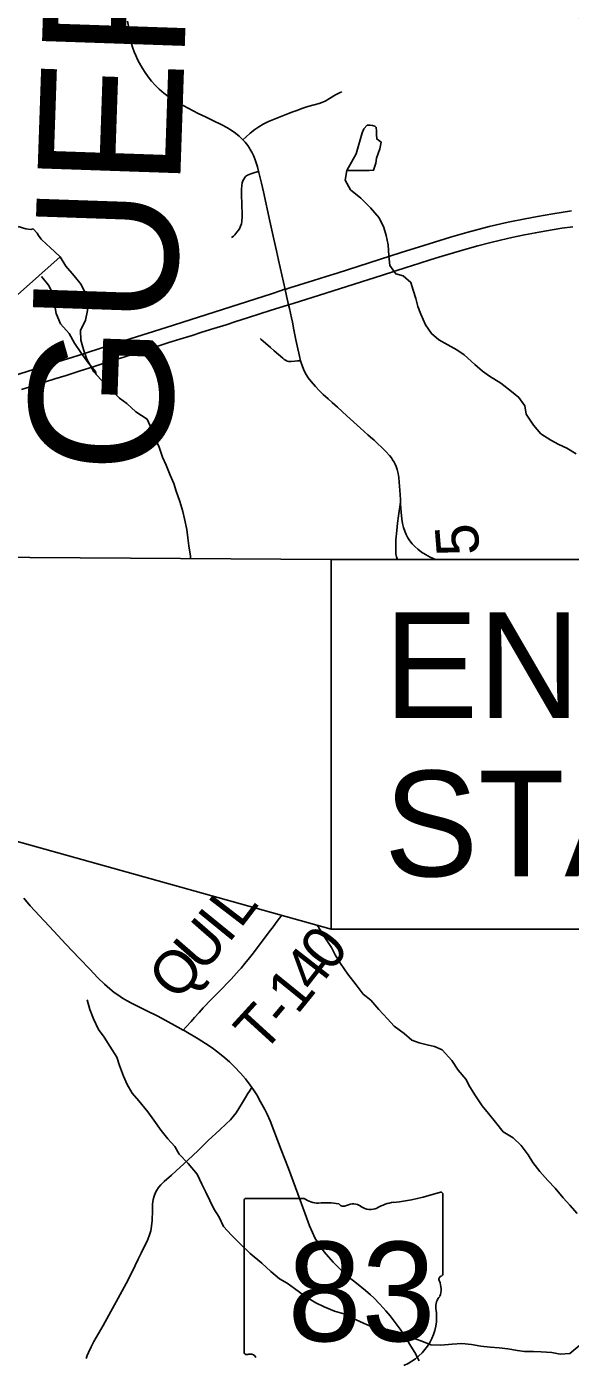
# Model space of a CAD drawing. Extents: x 0 to 34, y 0 to 22.
# Drawn here: x 28.753 to 29.474, y 15.353 to 17.117 of the extents above; entities that cross this region are included whole.
import ezdxf

# ---------------------------------------------------------------- set-up
doc = ezdxf.new("R2010")
doc.units = 0
for name, color, linetype in [('GM_X_Adjacent_County_Text', 7, 'Continuous'), ('GM_X_County_Road', 7, 'Continuous'), ('GM_X_Interstate_Route', 7, 'Continuous'), ('GM_X_Minor_Lake', 7, 'Continuous'), ('GM_X_Minor_River', 7, 'Continuous'), ('GM_X_Minor_River_Text', 7, 'Continuous'), ('GM_X_State_Location', 7, 'Continuous'), ('GM_X_State_Route', 7, 'Continuous'), ('GM_X_State_Shield', 7, 'Continuous'), ('GM_X_Township_Road', 7, 'Continuous'), ('GM_X_Township_Road_Text', 7, 'Continuous'), ('SH_Text', 7, 'Continuous')]:
    doc.layers.add(name, color=color, linetype=linetype)

msp = doc.modelspace()

# ---------------------------------------------------------------- linework, layer by layer
at = {"layer": 'GM_X_County_Road'}
for points in [[(28.9994, 16.9926), (28.9953, 16.9946), (28.9897, 16.9973), (28.9803, 17.002), (28.967, 17.0088), (28.9535, 17.0161), (28.9456, 17.021), (28.94, 17.0249), (28.9346, 17.029), (28.9286, 17.0342), (28.9233, 17.0394), (28.9184, 17.0449), (28.9138, 17.0507), (28.9099, 17.0563), (28.9059, 17.0625), (28.9022, 17.0688), (28.8998, 17.0735), (28.8973, 17.0788), (28.8952, 17.0838), (28.8933, 17.0896), (28.8918, 17.0946), (28.8905, 17.1014), (28.8882, 17.1154), (28.8866, 17.1241)], [(29.0394, 16.967), (29.0387, 16.9679), (29.0347, 16.9718), (29.0298, 16.9758), (29.0241, 16.9798), (29.0182, 16.9833), (29.0116, 16.9868), (28.9994, 16.9926)], [(29.0602, 16.925), (29.0587, 16.9311), (29.0563, 16.9389), (29.0538, 16.9453), (29.0514, 16.9504), (29.0492, 16.9542), (29.0482, 16.9557), (29.0458, 16.9593), (29.0424, 16.9637), (29.0394, 16.967)], [(29.116, 16.6737), (29.1144, 16.68), (29.1114, 16.6939), (29.1098, 16.7018), (29.1071, 16.7151), (29.1051, 16.725), (29.1039, 16.731), (29.1012, 16.7432), (29.1, 16.7482), (29.0973, 16.7602), (29.0954, 16.7686), (29.0867, 16.8074), (29.084, 16.8196), (29.0804, 16.8353), (29.0753, 16.859), (29.0666, 16.8978), (29.0639, 16.9093), (29.0605, 16.9238), (29.0602, 16.925)], [(29.1428, 16.6324), (29.1402, 16.6349), (29.1357, 16.6398), (29.13, 16.6464), (29.1262, 16.6512), (29.1232, 16.6558), (29.1207, 16.6607), (29.1184, 16.6664), (29.1162, 16.6728), (29.116, 16.6737)], [(29.2485, 16.4865), (29.2483, 16.49), (29.2476, 16.5024), (29.2468, 16.5129), (29.2462, 16.5191), (29.2453, 16.5247), (29.2442, 16.5296), (29.2427, 16.5338), (29.2414, 16.5367), (29.24, 16.5395), (29.238, 16.5425), (29.2365, 16.5451), (29.2338, 16.5485), (29.2291, 16.5536), (29.2247, 16.558), (29.2169, 16.5652), (29.2133, 16.5686), (29.2086, 16.5727), (29.2053, 16.5756), (29.1952, 16.5847), (29.1773, 16.6011), (29.1648, 16.6123), (29.158, 16.6185), (29.1524, 16.6235), (29.146, 16.6293), (29.1428, 16.6324)], [(29.2949, 16.4104), (29.2879, 16.4136), (29.2814, 16.417), (29.2762, 16.4203), (29.2713, 16.4241), (29.2672, 16.4277), (29.2639, 16.4313), (29.2608, 16.4351), (29.2582, 16.4392), (29.2559, 16.4435), (29.254, 16.448), (29.2524, 16.4529), (29.2511, 16.458), (29.2502, 16.4641), (29.2493, 16.4733), (29.2486, 16.4832), (29.2485, 16.4865)], [(28.8316, 15.3512), (28.833, 15.3552), (28.8346, 15.3592), (28.8382, 15.3664), (28.842, 15.3734), (28.8543, 15.395), (28.8618, 15.4086), (28.874, 15.431), (28.8847, 15.4506), (28.8921, 15.4649), (28.8966, 15.4745), (28.9006, 15.4829), (28.9022, 15.4862), (28.9044, 15.4907), (28.9077, 15.4973), (28.9124, 15.5068), (28.9153, 15.5138), (28.9172, 15.5204), (28.9183, 15.5266), (28.919, 15.5341), (28.9194, 15.5472), (28.9198, 15.5558), (28.9205, 15.5618), (28.9217, 15.5665), (28.9234, 15.571), (28.9252, 15.5744), (28.9276, 15.5776), (28.9307, 15.5813), (28.9349, 15.5857), (28.9446, 15.5943), (28.9511, 15.6), (28.9562, 15.6046), (28.9608, 15.6088), (28.9663, 15.6139), (28.9735, 15.6207), (28.9798, 15.6266), (28.9936, 15.6399), (29.0089, 15.6542), (29.0174, 15.6623), (29.0228, 15.6676), (29.0266, 15.6718), (29.0304, 15.6768), (29.0342, 15.6825), (29.039, 15.6905), (29.0428, 15.697), (29.046, 15.7022), (29.0483, 15.7055), (29.0515, 15.7102)]]:
    msp.add_lwpolyline(points, dxfattribs=at)
at = {"layer": 'GM_X_Interstate_Route'}
for points in [[(28.6908, 16.6398), (28.7743, 16.6663), (28.8211, 16.6811), (28.8744, 16.6981), (28.9377, 16.7182), (29.0774, 16.7628), (29.0904, 16.767), (29.0939, 16.7683), (29.0954, 16.7686), (29.0957, 16.7687), (29.1017, 16.7705), (29.1331, 16.7805), (29.1497, 16.7857), (29.1646, 16.7901), (29.2491, 16.8174), (29.2793, 16.827), (29.3149, 16.8379), (29.3364, 16.8441), (29.3658, 16.8519), (29.3912, 16.8578), (29.4137, 16.8624), (29.4302, 16.8655), (29.4504, 16.869), (29.475, 16.8727)], [(28.7459, 16.6357), (28.7631, 16.6412), (28.7779, 16.6459), (28.7903, 16.6499), (28.8051, 16.6545), (28.8223, 16.66), (28.8424, 16.6664), (28.8666, 16.6742), (28.8814, 16.6789), (28.9027, 16.6858), (28.9205, 16.6915), (28.9252, 16.693), (28.9412, 16.698), (28.956, 16.7027), (28.9721, 16.7077), (28.9851, 16.7118), (29.0011, 16.7168), (29.0171, 16.7218), (29.0301, 16.726), (29.0455, 16.7309), (29.0621, 16.7361), (29.0757, 16.7405), (29.1, 16.7482), (29.1059, 16.75), (29.1492, 16.7637), (29.2244, 16.7875), (29.2558, 16.7975), (29.2729, 16.803), (29.2889, 16.8081), (29.3038, 16.8126), (29.3186, 16.8171), (29.3336, 16.8214), (29.3509, 16.8262), (29.3666, 16.8304), (29.3811, 16.834), (29.3962, 16.8374), (29.4126, 16.8409), (29.4273, 16.8438), (29.4395, 16.846), (29.4623, 16.8496), (29.477, 16.8517)]]:
    msp.add_lwpolyline(points, dxfattribs=at)
at = {"layer": 'GM_X_Minor_Lake'}
for points in [[(29.1771, 16.9265), (29.2067, 16.9263), (29.2128, 16.9267), (29.2157, 16.9359), (29.2168, 16.9427), (29.2187, 16.9488), (29.2209, 16.9549), (29.2227, 16.964), (29.2193, 16.9663), (29.217, 16.9681), (29.2166, 16.9738), (29.2166, 16.9788), (29.2162, 16.9833), (29.2143, 16.9852), (29.2112, 16.9859), (29.2082, 16.9863), (29.2044, 16.9863)], [(29.2044, 16.9863), (29.1999, 16.9817), (29.1976, 16.9764), (29.1895, 16.9482), (29.1771, 16.9265)], [(29.1771, 16.9265), (29.2067, 16.9263), (29.2128, 16.9267), (29.2157, 16.9359), (29.2168, 16.9427), (29.2187, 16.9488), (29.2209, 16.9549), (29.2227, 16.964), (29.2193, 16.9663), (29.217, 16.9681), (29.2166, 16.9738), (29.2166, 16.9788), (29.2162, 16.9833), (29.2143, 16.9852), (29.2112, 16.9859), (29.2082, 16.9863), (29.204, 16.9863)], [(28.7416, 16.8522), (28.7394, 16.8495), (28.736, 16.8461), (28.7337, 16.8423), (28.7311, 16.8377), (28.7274, 16.8324), (28.7263, 16.8263), (28.7256, 16.8168), (28.726, 16.8096), (28.7264, 16.8047), (28.7235, 16.7948), (28.7269, 16.7853), (28.7338, 16.7732), (28.7404, 16.7615), (28.7973, 16.8116)], [(28.7973, 16.8116), (28.7835, 16.8248), (28.7797, 16.8282), (28.7721, 16.8353), (28.7683, 16.8399), (28.7667, 16.8433), (28.7614, 16.8489), (28.7583, 16.8481), (28.7515, 16.8489), (28.7416, 16.8522)]]:
    msp.add_lwpolyline(points, dxfattribs=at)
at = {"layer": 'GM_X_Minor_River'}
for points in [[(29.2654, 16.7677), (29.2623, 16.7779), (29.252, 16.7866), (29.2421, 16.7892), (29.2341, 16.8001), (29.2329, 16.813), (29.232, 16.8278), (29.2293, 16.8403), (29.2262, 16.8505), (29.22, 16.8634), (29.2086, 16.8766), (29.1956, 16.8894), (29.1822, 16.9007), (29.1749, 16.9136), (29.1771, 16.9265)], [(28.9701, 16.4116), (28.9698, 16.415), (28.9678, 16.4286), (28.9666, 16.4392), (28.965, 16.4502), (28.9619, 16.4642), (28.9599, 16.4741), (28.956, 16.4874), (28.951, 16.501), (28.9479, 16.5112), (28.9429, 16.5222), (28.9379, 16.5354), (28.9329, 16.546), (28.9283, 16.5593), (28.9225, 16.5718), (28.9178, 16.5847), (28.9125, 16.5964), (28.8976, 16.6065), (28.8854, 16.6175), (28.8759, 16.6246), (28.8633, 16.6374), (28.8511, 16.6491), (28.8419, 16.6593), (28.8327, 16.6763), (28.828, 16.6888), (28.8246, 16.7013), (28.8241, 16.7142), (28.8308, 16.7279), (28.8334, 16.7405), (28.8333, 16.753), (28.831, 16.7625), (28.8252, 16.775), (28.8156, 16.7867), (28.8049, 16.7995), (28.7973, 16.8116)], [(28.8451, 16.6557), (28.8442, 16.6597), (28.8346, 16.671), (28.8247, 16.685), (28.8162, 16.6975), (28.8093, 16.7103), (28.7975, 16.7228), (28.7917, 16.7368), (28.7897, 16.7497), (28.7877, 16.7622), (28.7816, 16.7743), (28.7724, 16.7856)], [(29.4811, 16.5505), (29.4689, 16.558), (29.4582, 16.5629), (29.4476, 16.5689), (29.4346, 16.5771), (29.4247, 16.5885), (29.4151, 16.6032), (29.4132, 16.6142), (29.4055, 16.6251), (29.3956, 16.6334), (29.3815, 16.6443), (29.3666, 16.6537), (29.3571, 16.6601), (29.3468, 16.6692), (29.3327, 16.682), (29.3232, 16.6884), (29.311, 16.6951), (29.2992, 16.7019), (29.2893, 16.7101), (29.2816, 16.7215), (29.2755, 16.7359), (29.2716, 16.7461), (29.2689, 16.7567), (29.2654, 16.7677)], [(29.4826, 15.5435), (29.4731, 15.5544), (29.4639, 15.5642), (29.4536, 15.5767), (29.4437, 15.5869), (29.433, 15.5989), (29.4238, 15.611), (29.4176, 15.6209), (29.4085, 15.6333), (29.3978, 15.6435), (29.3844, 15.6518), (29.3745, 15.6642), (29.3649, 15.6759), (29.3565, 15.6861), (29.3477, 15.6993), (29.3404, 15.7111), (29.3351, 15.7213), (29.3247, 15.7333), (29.3163, 15.7462), (29.3037, 15.7602), (29.2934, 15.7646), (29.2839, 15.7668), (29.2733, 15.7694), (29.2634, 15.7732), (29.2531, 15.7818), (29.2402, 15.7916), (29.231, 15.8014), (29.2196, 15.8139), (29.2089, 15.8263), (29.1989, 15.8342), (29.1898, 15.8463), (29.1787, 15.8607), (29.1687, 15.8746), (29.1618, 15.8864), (29.1568, 15.8962), (29.148, 15.9094), (29.1396, 15.923), (29.1372, 15.9258)], [(29.4861, 15.3685), (29.4729, 15.3578), (29.46, 15.3569), (29.449, 15.3588), (29.435, 15.3598), (29.4247, 15.3601), (29.413, 15.3604), (29.4035, 15.3615), (29.3906, 15.3637), (29.3792, 15.3651), (29.3671, 15.3662), (29.3549, 15.3676), (29.3424, 15.3694), (29.3299, 15.3709), (29.317, 15.37), (29.3018, 15.3688), (29.2886, 15.3691), (29.279, 15.3732), (29.2669, 15.3777), (29.2547, 15.3829), (29.2441, 15.3866), (29.2312, 15.3896), (29.2213, 15.3903), (29.2114, 15.3928), (29.1993, 15.3981), (29.1848, 15.4044), (29.1734, 15.4104), (29.1609, 15.4138), (29.1472, 15.4197), (29.1361, 15.425), (29.1228, 15.4329), (29.108, 15.4438), (29.0981, 15.4509), (29.0878, 15.4565), (29.0767, 15.4663), (29.0645, 15.4773), (29.0493, 15.4901), (29.0355, 15.5033), (29.0244, 15.5146), (29.0138, 15.5259), (29.008, 15.5384), (29.0011, 15.5497), (28.9903, 15.5717), (28.9849, 15.5822), (28.9788, 15.5955), (28.9669, 15.6098), (28.9551, 15.6219), (28.949, 15.6321), (28.9398, 15.6423), (28.931, 15.6532), (28.9214, 15.6672), (28.9134, 15.6782), (28.9015, 15.6925), (28.8927, 15.7027), (28.8858, 15.7144), (28.8812, 15.7254), (28.8758, 15.7394), (28.8723, 15.7508), (28.8631, 15.7651), (28.8555, 15.7772), (28.8482, 15.7874), (28.8413, 15.8014), (28.8363, 15.8139), (28.8331, 15.8268)]]:
    msp.add_lwpolyline(points, dxfattribs=at)
at = {"layer": 'GM_X_State_Route'}
msp.add_lwpolyline([(29.2732, 15.3479), (29.2673, 15.3588), (29.2623, 15.3674), (29.2545, 15.38), (29.2479, 15.3898), (29.2414, 15.3988), (29.2345, 15.4076), (29.229, 15.4142), (29.2212, 15.4229), (29.213, 15.4313), (29.2085, 15.4354), (29.202, 15.441), (29.19, 15.4508), (29.1803, 15.4586), (29.1748, 15.4636), (29.1657, 15.4721), (29.1592, 15.4788), (29.1529, 15.4857), (29.1473, 15.4924), (29.1425, 15.4989), (29.1384, 15.5052), (29.135, 15.5111), (29.1317, 15.5179), (29.1278, 15.5271), (29.1218, 15.5428), (29.109, 15.5777), (29.0998, 15.6028), (29.0901, 15.6277), (29.0805, 15.6533), (29.0755, 15.666), (29.0715, 15.675), (29.0686, 15.6812), (29.063, 15.6915), (29.0578, 15.7007), (29.0535, 15.7074), (29.0515, 15.7102), (29.0492, 15.7135), (29.0427, 15.7217), (29.0362, 15.7292), (29.0282, 15.7378), (29.0215, 15.7442), (29.0127, 15.752), (29.0045, 15.7586), (28.9985, 15.763), (28.9898, 15.7688), (28.9803, 15.7748), (28.9616, 15.7858), (28.9602, 15.7865), (28.9534, 15.7903), (28.9366, 15.7996), (28.9256, 15.8053), (28.9123, 15.812), (28.8918, 15.8223), (28.8862, 15.8252), (28.8798, 15.829), (28.8735, 15.8331), (28.8689, 15.8363), (28.8631, 15.841), (28.8561, 15.8473), (28.8472, 15.856), (28.8364, 15.8672), (28.8227, 15.8816), (28.8048, 15.9005), (28.7887, 15.9177), (28.7638, 15.9445), (28.7575, 15.9514), (28.7491, 15.9614)], dxfattribs=at)
at = {"layer": 'GM_X_State_Shield'}
for p, q in [((29.1208, 15.5634), (29.0436, 15.5634)), ((29.3046, 15.4637), (29.3046, 15.5684)), ((29.041, 15.56), (29.041, 15.3599)), ((29.3046, 15.4637), (29.3046, 15.4637))]:
    msp.add_line(p, q, dxfattribs=at)
for centre, radius, start, end in [((29.044, 15.5604), 0.00305, 98.1301, 188.1301), ((29.1392, 15.5866), 0.0296, 231.6195, 271.1119), ((29.2107, 15.8362), 0.2796, 275.8445, 288.9065), ((29.3017, 15.5688), 0.00294, 351.8621, 97.738), ((29.149, 15.4511), 0.1064, 80.4867, 94.9883), ((29.1731, 15.5614), 0.00855, 219.7921, 297.1024), ((29.1857, 15.5383), 0.0178, 54.4667, 119.1411), ((29.2086, 15.57), 0.0214, 233.8562, 294.8282), ((29.2464, 15.5023), 0.0563, 97.3462, 120.7689), ((29.3039, 15.456), 0.00454, 107.944, 210.337), ((29.3015, 15.4633), 0.00314, 289.6038, 7.7341), ((29.275, 15.4428), 0.0273, 340.033, 23.6496), ((29.3151, 15.4199), 0.0198, 136.8065, 186.9296), ((29.2264, 15.4066), 0.0699, 292.3089, 8.9858), ((29.044, 15.3594), 0.00308, 171.9584, 258.3066), ((29.0445, 15.3799), 0.0235, 267.339, 280.6039), ((29.0493, 15.3483), 0.00848, 29.7484, 93.2717)]:
    msp.add_arc(centre, radius, start, end, dxfattribs=at)
at = {"layer": 'GM_X_Township_Road'}
for points in [[(29.0394, 16.967), (29.0435, 16.9707), (29.049, 16.9757), (29.0553, 16.9807), (29.0604, 16.9843), (29.0662, 16.9879), (29.0735, 16.9913), (29.0844, 16.9958), (29.0913, 16.9985), (29.1, 17.0019), (29.1057, 17.0042), (29.1098, 17.0056), (29.1144, 17.0072), (29.1156, 17.0077), (29.1191, 17.0089), (29.1256, 17.011), (29.1339, 17.0132), (29.1404, 17.015), (29.1439, 17.0163), (29.1484, 17.0184), (29.1542, 17.0218), (29.1622, 17.0266), (29.1683, 17.0297), (29.1706, 17.0307)], [(29.0242, 16.8376), (29.0253, 16.8381), (29.0268, 16.8392), (29.0286, 16.8409), (29.0313, 16.8443), (29.0335, 16.8473), (29.0352, 16.8498), (29.0364, 16.8525), (29.0375, 16.8556), (29.0381, 16.8593), (29.0384, 16.8649), (29.0384, 16.8698), (29.0384, 16.8716), (29.0382, 16.8778), (29.0379, 16.8847), (29.0377, 16.8908), (29.0376, 16.9013), (29.038, 16.9062), (29.0386, 16.9098), (29.0395, 16.9127), (29.0406, 16.9149), (29.042, 16.9169), (29.0431, 16.9182), (29.0444, 16.9191), (29.0456, 16.92), (29.0477, 16.9209), (29.0501, 16.9218), (29.0554, 16.9235), (29.0602, 16.925)], [(29.1031, 16.6729), (29.1014, 16.6729), (29.0998, 16.6731), (29.0981, 16.6735), (29.0967, 16.6742), (29.0951, 16.6751), (29.0941, 16.6758), (29.0922, 16.6773), (29.081, 16.6872), (29.0759, 16.6916), (29.0693, 16.6974), (29.0638, 16.7024), (29.0624, 16.7036)], [(29.116, 16.6737), (29.1119, 16.6737), (29.1083, 16.6734), (29.1033, 16.6729), (29.1031, 16.6729)], [(29.2441, 16.4104), (29.2438, 16.4112), (29.243, 16.4142), (29.2424, 16.4179), (29.2421, 16.4228), (29.2422, 16.4297), (29.2424, 16.4365), (29.2435, 16.4488), (29.2444, 16.4587), (29.2459, 16.4685), (29.2485, 16.4865)], [(29.0344, 15.8659), (29.037, 15.8688), (29.0422, 15.875), (29.048, 15.8822), (29.0533, 15.8891), (29.0649, 15.9043), (29.0719, 15.9137), (29.0741, 15.9166), (29.0794, 15.9234), (29.085, 15.9308), (29.0909, 15.9387)], [(28.9602, 15.7865), (28.9642, 15.7908), (28.9709, 15.7981), (28.9755, 15.8032), (28.9813, 15.8097), (28.9866, 15.8158), (28.9972, 15.827), (29.0078, 15.8375), (29.0237, 15.8541), (29.0344, 15.8659)]]:
    msp.add_lwpolyline(points, dxfattribs=at)
at = {"layer": 'SH_Text'}
for points in [[(27.359, 16.4225), (29.1566, 15.9204), (29.1566, 16.4104)], [(29.1566, 15.9204), (30.7042, 15.9204), (30.7042, 16.4104), (29.1566, 16.4104)]]:
    msp.add_lwpolyline(points, close=True, dxfattribs=at)

# ---------------------------------------------------------------- texts
at = {"layer": 'GM_X_Adjacent_County_Text'}
msp.add_text('GUERNSEY COUNTY', height=0.189394, rotation=88.0332, dxfattribs=at).set_placement((28.9429, 16.5222))
at = {"layer": 'GM_X_Minor_River_Text'}
msp.add_text('Crooked', height=0.09469, rotation=332.1843, dxfattribs=at).set_placement((29.2254, 17.2651))
at = {"layer": 'GM_X_State_Location'}
for s in ['s', 'r']:
    msp.add_text(s, height=0.000189, dxfattribs=at).set_placement((29.1698, 15.4466))
msp.add_text('83', height=0.000189, rotation=0, dxfattribs=at).set_placement((29.1221, 15.4328))
at = {"layer": 'GM_X_State_Shield'}
msp.add_text('83', height=0.13184, dxfattribs=at).set_placement((29.0987, 15.374))
at = {"layer": 'GM_X_Township_Road_Text'}
for s, rotation, p in [('5', 94.6262, (29.3535, 16.4177)), ('L', 52.5165, (29.0361, 15.9199)), ('U', 48.8815, (28.986, 15.8611)), ('I', 50.8445, (29.0202, 15.9004)), ('0', 52.3539, (29.1559, 15.8619)), ('Q', 47.9094, (28.9517, 15.8232)), ('4', 52.0676, (29.1342, 15.834)), ('1', 50.9626, (29.1114, 15.8059)), ('T', 47.6617, (29.0654, 15.754)), ('-', 49.8051, (29.0956, 15.7871))]:
    msp.add_text(s, height=0.0568, rotation=rotation, dxfattribs=at).set_placement(p)
at = {"layer": 'SH_Text'}
for s, p in [('END PROJECT', (29.2266, 16.2004)), ('STA. 692+70', (29.2266, 15.9904))]:
    msp.add_text(s, height=0.14, dxfattribs=at).set_placement(p)

doc.saveas('drawing.dxf')
